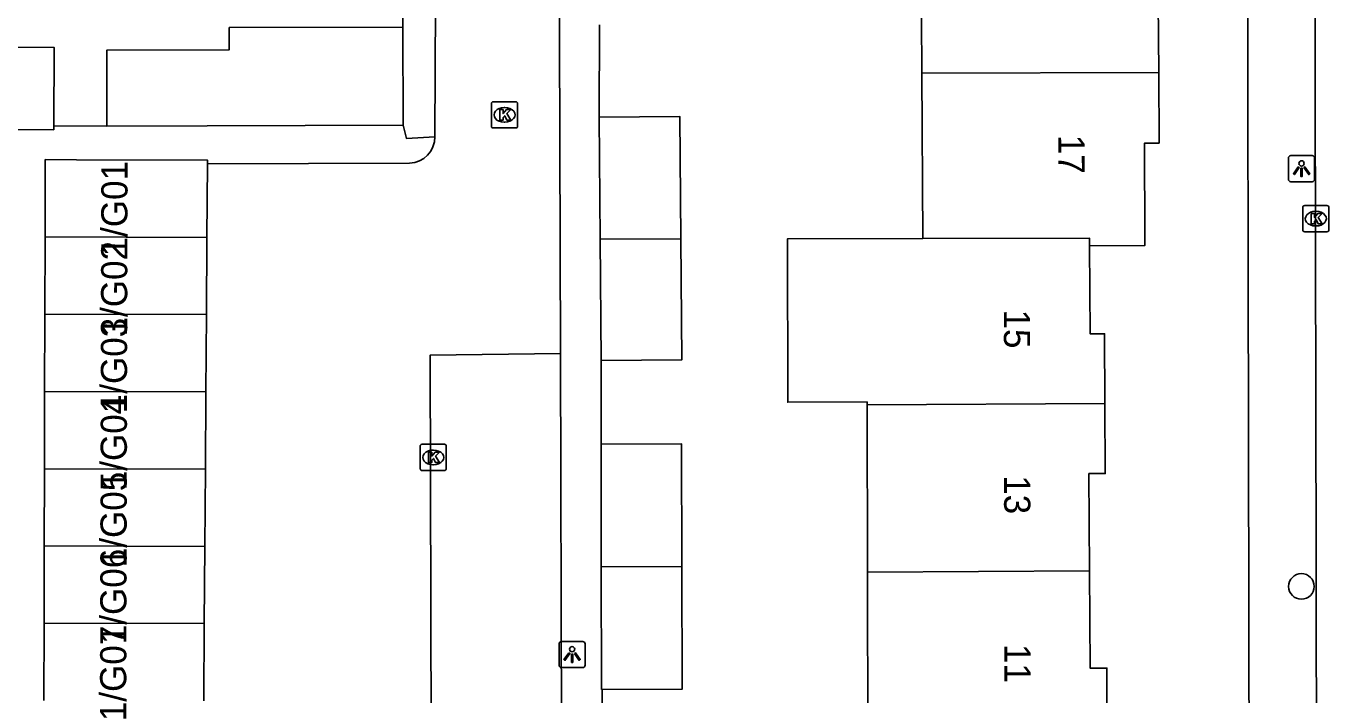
# Model space of a CAD drawing. Extents: x 160732 to 162105, y 387428 to 388479.
# Drawn here: x 161107.53 to 161157.26, y 387901.19 to 387926.72 of the extents above; entities that cross this region are included whole.
import ezdxf

# ---------------------------------------------------------------- set-up
doc = ezdxf.new("R2010")
doc.units = 0
for name, color, linetype in [('IMGEO_Boom', 7, 'Continuous'), ('IMGEO_Kolk', 7, 'Continuous'), ('IMGEO_Lichtpunt', 7, 'Continuous'), ('IMGEO_Muur', 7, 'Continuous'), ('IMGEO_Pand', 7, 'Continuous'), ('IMGEO_Pand_nummerreeks', 7, 'Continuous'), ('IMGEO_Rijbaan_lokaal_open', 7, 'Continuous'), ('IMGEO_Voetpad_open', 7, 'Continuous')]:
    doc.layers.add(name, color=color, linetype=linetype)

msp = doc.modelspace()

# ---------------------------------------------------------------- linework, layer by layer
at = {"layer": 'IMGEO_Boom'}
msp.add_circle((161156.212, 387905.33), 0.489, dxfattribs=at)
at = {"layer": 'IMGEO_Kolk'}
for p, q in [((161125.292, 387922.907), (161125.292, 387923.759)), ((161125.367, 387923.833), (161126.219, 387923.833)), ((161125.78, 387923.613), (161125.805, 387923.613)), ((161126.293, 387923.759), (161126.293, 387922.907)), ((161125.803, 387923.053), (161125.778, 387923.053)), ((161126.219, 387922.833), (161125.367, 387922.833)), ((161156.262, 387918.946), (161156.262, 387919.798)), ((161156.337, 387919.872), (161157.189, 387919.872)), ((161156.75, 387919.652), (161156.775, 387919.652)), ((161157.263, 387919.798), (161157.263, 387918.946)), ((161156.773, 387919.092), (161156.748, 387919.092)), ((161157.189, 387918.872), (161156.337, 387918.872)), ((161122.57, 387909.83), (161122.57, 387910.682)), ((161122.645, 387910.756), (161123.497, 387910.756)), ((161123.058, 387910.536), (161123.083, 387910.536)), ((161123.571, 387910.682), (161123.571, 387909.83)), ((161123.081, 387909.976), (161123.056, 387909.976)), ((161123.497, 387909.756), (161122.645, 387909.756))]:
    msp.add_line(p, q, dxfattribs=at)
for points in [[(161125.292, 387922.907), (161125.292, 387923.759)], [(161125.367, 387923.833), (161126.219, 387923.833)], [(161125.613, 387923.533), (161125.736, 387923.533), (161125.736, 387923.382), (161125.866, 387923.533), (161126.03, 387923.533), (161125.884, 387923.382), (161126.037, 387923.133), (161125.885, 387923.133), (161125.8, 387923.297), (161125.736, 387923.23), (161125.736, 387923.133), (161125.613, 387923.133), (161125.613, 387923.533)], [(161126.293, 387923.759), (161126.293, 387922.907)], [(161126.219, 387922.833), (161125.367, 387922.833)], [(161156.262, 387918.946), (161156.262, 387919.798)], [(161156.337, 387919.872), (161157.189, 387919.872)], [(161156.583, 387919.572), (161156.706, 387919.572), (161156.706, 387919.421), (161156.836, 387919.572), (161157, 387919.572), (161156.854, 387919.421), (161157.007, 387919.172), (161156.855, 387919.172), (161156.77, 387919.336), (161156.706, 387919.269), (161156.706, 387919.172), (161156.583, 387919.172), (161156.583, 387919.572)], [(161157.263, 387919.798), (161157.263, 387918.946)], [(161157.189, 387918.872), (161156.337, 387918.872)], [(161122.57, 387909.83), (161122.57, 387910.682)], [(161122.645, 387910.756), (161123.497, 387910.756)], [(161122.891, 387910.456), (161123.014, 387910.456), (161123.014, 387910.305), (161123.144, 387910.456), (161123.308, 387910.456), (161123.162, 387910.305), (161123.315, 387910.056), (161123.163, 387910.056), (161123.078, 387910.22), (161123.014, 387910.153), (161123.014, 387910.056), (161122.891, 387910.056), (161122.891, 387910.456)], [(161123.571, 387910.682), (161123.571, 387909.83)], [(161123.497, 387909.756), (161122.645, 387909.756)]]:
    msp.add_lwpolyline(points, dxfattribs=at)
for centre, start, end in [((161125.369, 387923.757), 91.552, 178.448), ((161125.369, 387923.757), 91.552, 178.448), ((161126.217, 387923.757), 1.552, 88.448), ((161126.217, 387923.757), 1.552, 88.448), ((161125.369, 387922.909), 181.552, 268.448), ((161125.369, 387922.909), 181.552, 268.448), ((161126.217, 387922.909), 271.552, 358.448), ((161126.217, 387922.909), 271.552, 358.448), ((161156.339, 387919.796), 91.552, 178.448), ((161156.339, 387919.796), 91.552, 178.448), ((161157.187, 387919.796), 1.552, 88.448), ((161157.187, 387919.796), 1.552, 88.448), ((161156.339, 387918.948), 181.552, 268.448), ((161156.339, 387918.948), 181.552, 268.448), ((161157.187, 387918.948), 271.552, 358.448), ((161157.187, 387918.948), 271.552, 358.448), ((161122.647, 387910.68), 91.552, 178.448), ((161122.647, 387910.68), 91.552, 178.448), ((161123.495, 387910.68), 1.552, 88.448), ((161123.495, 387910.68), 1.552, 88.448), ((161122.647, 387909.832), 181.552, 268.448), ((161122.647, 387909.832), 181.552, 268.448), ((161123.495, 387909.832), 271.552, 358.448), ((161123.495, 387909.832), 271.552, 358.448)]:
    msp.add_arc(centre, 0.0765, start, end, dxfattribs=at)
for centre, major_axis, ratio, start_param, end_param in [((161125.779, 387923.333), (-0.387, 0.002), 0.722429, 4.712389, 7.853982), ((161125.804, 387923.333), (-0.39, 0.002), 0.717154, 1.570796, 4.712389), ((161156.749, 387919.372), (-0.387, 0.002), 0.722429, 4.712389, 7.853982), ((161156.774, 387919.372), (-0.39, 0.002), 0.717154, 1.570796, 4.712389), ((161123.057, 387910.256), (-0.387, 0.002), 0.722429, 4.712389, 7.853982), ((161123.082, 387910.256), (-0.39, 0.002), 0.717154, 1.570796, 4.712389)]:
    msp.add_ellipse(centre, major_axis=major_axis, ratio=ratio, start_param=start_param, end_param=end_param, dxfattribs=at)
at = {"layer": 'IMGEO_Lichtpunt'}
for p, q in [((161155.718, 387921.683), (161155.718, 387920.876)), ((161155.718, 387921.683), (161155.718, 387920.876)), ((161156.62, 387921.778), (161155.812, 387921.778)), ((161156.62, 387921.778), (161155.812, 387921.778)), ((161156.714, 387920.876), (161156.714, 387921.683)), ((161156.714, 387920.876), (161156.714, 387921.683)), ((161155.812, 387920.782), (161156.62, 387920.782)), ((161155.812, 387920.782), (161156.62, 387920.782)), ((161127.875, 387903.134), (161127.875, 387902.327)), ((161127.875, 387903.134), (161127.875, 387902.327)), ((161128.777, 387903.229), (161127.969, 387903.229)), ((161128.777, 387903.229), (161127.969, 387903.229)), ((161128.871, 387902.327), (161128.871, 387903.134)), ((161128.871, 387902.327), (161128.871, 387903.134)), ((161127.969, 387902.233), (161128.777, 387902.233)), ((161127.969, 387902.233), (161128.777, 387902.233))]:
    msp.add_line(p, q, dxfattribs=at)
for points in [[(161156.092, 387921.347), (161156.131, 387921.319), (161155.943, 387921.057), (161155.905, 387921.084), (161156.092, 387921.347)], [(161156.194, 387921.299), (161156.241, 387921.299), (161156.241, 387920.977), (161156.194, 387920.977), (161156.194, 387921.299)], [(161156.304, 387921.319), (161156.342, 387921.346), (161156.529, 387921.084), (161156.49, 387921.056), (161156.304, 387921.319)], [(161128.249, 387902.798), (161128.288, 387902.77), (161128.1, 387902.508), (161128.062, 387902.535), (161128.249, 387902.798)], [(161128.351, 387902.75), (161128.398, 387902.75), (161128.398, 387902.428), (161128.351, 387902.428), (161128.351, 387902.75)], [(161128.461, 387902.77), (161128.499, 387902.797), (161128.686, 387902.535), (161128.647, 387902.507), (161128.461, 387902.77)]]:
    msp.add_lwpolyline(points, dxfattribs=at)
for centre in [(161156.217, 387921.481), (161128.374, 387902.932)]:
    msp.add_circle(centre, 0.0994, dxfattribs=at)
for centre, start, end in [((161155.812, 387921.683), 90, 180), ((161155.812, 387921.683), 90, 180), ((161156.62, 387921.683), 0, 90), ((161156.62, 387921.683), 0, 90), ((161155.812, 387920.876), 180, 270), ((161155.812, 387920.876), 180, 270), ((161156.62, 387920.876), 270, 0), ((161156.62, 387920.876), 270, 360), ((161127.969, 387903.134), 90, 180), ((161127.969, 387903.134), 90, 180), ((161128.777, 387903.134), 0, 90), ((161128.777, 387903.134), 0, 90), ((161127.969, 387902.327), 180, 270), ((161127.969, 387902.327), 180, 270), ((161128.777, 387902.327), 270, 0), ((161128.777, 387902.327), 270, 360)]:
    msp.add_arc(centre, 0.0946, start, end, dxfattribs=at)
at = {"layer": 'IMGEO_Muur'}
msp.add_lwpolyline([(161121.921, 387927.626), (161121.915, 387926.685)], dxfattribs=at)
at = {"layer": 'IMGEO_Pand'}
for points in [[(161141.685, 387931.353), (161141.721, 387924.932)], [(161150.765, 387924.948), (161150.75, 387927.642), (161150.13, 387927.638), (161150.109, 387931.368)], [(161110.618, 387922.905), (161110.608, 387925.803), (161115.287, 387925.818), (161115.285, 387926.663), (161121.915, 387926.685)], [(161121.928, 387922.943), (161121.915, 387926.685)], [(161108.586, 387922.912), (161108.596, 387925.912), (161102.178, 387925.935)], [(161150.765, 387924.948), (161141.721, 387924.932)], [(161141.721, 387924.932), (161141.757, 387918.614)], [(161148.128, 387918.338), (161150.24, 387918.35), (161150.238, 387918.629), (161150.218, 387922.251), (161150.781, 387922.254), (161150.765, 387924.948)], [(161108.586, 387922.912), (161108.585, 387922.765), (161102.19, 387922.788)], [(161121.928, 387922.943), (161114.448, 387922.918), (161110.618, 387922.905)], [(161129.402, 387923.242), (161132.486, 387923.268), (161132.524, 387918.598)], [(161129.441, 387918.592), (161129.402, 387923.242)], [(161114.453, 387921.466), (161114.454, 387921.609), (161109.455, 387921.622), (161108.261, 387921.624), (161108.253, 387918.674)], [(161114.434, 387918.658), (161114.453, 387921.466)], [(161108.253, 387918.674), (161108.246, 387915.724)], [(161108.253, 387918.674), (161114.434, 387918.658)], [(161114.413, 387915.708), (161114.434, 387918.658)], [(161129.441, 387918.592), (161132.524, 387918.598)], [(161129.479, 387913.961), (161129.441, 387918.592)], [(161132.524, 387918.598), (161132.562, 387913.986), (161129.479, 387913.961)], [(161141.757, 387918.614), (161136.601, 387918.605), (161136.605, 387912.363), (161139.633, 387912.373), (161139.633, 387912.259)], [(161141.757, 387918.614), (161148.126, 387918.625), (161148.128, 387918.338)], [(161148.712, 387912.31), (161148.697, 387914.979), (161148.147, 387914.976), (161148.128, 387918.338)], [(161108.246, 387915.724), (161108.238, 387912.775)], [(161114.413, 387915.708), (161108.246, 387915.724)], [(161114.393, 387912.759), (161114.413, 387915.708)], [(161108.238, 387912.775), (161108.23, 387909.825)], [(161114.393, 387912.759), (161108.238, 387912.775)], [(161114.373, 387909.809), (161114.393, 387912.759)], [(161148.712, 387912.31), (161139.633, 387912.259)], [(161139.633, 387912.259), (161139.648, 387905.871)], [(161148.122, 387905.922), (161148.101, 387909.637), (161148.726, 387909.641), (161148.712, 387912.31)], [(161129.479, 387910.767), (161132.553, 387910.772), (161132.562, 387906.088)], [(161129.488, 387906.082), (161129.479, 387910.767)], [(161108.23, 387909.825), (161108.223, 387906.875)], [(161108.23, 387909.825), (161114.373, 387909.809)], [(161114.353, 387906.859), (161114.373, 387909.809)], [(161108.223, 387906.875), (161108.215, 387903.925)], [(161114.353, 387906.859), (161108.223, 387906.875)], [(161114.332, 387903.909), (161114.353, 387906.859)], [(161129.488, 387906.082), (161132.562, 387906.088)], [(161129.516, 387901.399), (161129.497, 387901.399), (161129.488, 387906.082)], [(161132.562, 387906.088), (161132.57, 387901.405), (161129.516, 387901.399)], [(161139.648, 387905.871), (161148.122, 387905.922)], [(161139.648, 387905.871), (161139.662, 387899.466)], [(161148.799, 387899.508), (161148.787, 387902.215), (161148.143, 387902.212), (161148.122, 387905.922)], [(161108.208, 387900.976), (161108.215, 387903.925)], [(161108.215, 387903.925), (161114.332, 387903.909)], [(161114.332, 387903.909), (161114.312, 387900.96)]]:
    msp.add_lwpolyline(points, dxfattribs=at)
at = {"layer": 'IMGEO_Rijbaan_lokaal_open'}
for points in [[(161156.704, 387942.547), (161156.776, 387906.254), (161156.817, 387879.896)], [(161127.926, 387914.225), (161127.885, 387930.449)], [(161123.156, 387927.578), (161123.128, 387922.5)], [(161114.453, 387921.466), (161122.168, 387921.485)], [(161123.049, 387880.357), (161122.958, 387914.162), (161127.926, 387914.225)]]:
    msp.add_lwpolyline(points, dxfattribs=at)
msp.add_arc((161122.14, 387922.473), 0.989, 271.6458, 1.5446, dxfattribs=at)
at = {"layer": 'IMGEO_Voetpad_open'}
for points in [[(161154.127, 387944.025), (161154.217, 387897.663), (161154.171, 387880.36)], [(161121.915, 387926.685), (161121.921, 387927.626)], [(161129.42, 387926.772), (161129.402, 387923.242)], [(161110.618, 387922.905), (161108.586, 387922.912)], [(161123.128, 387922.5), (161122.048, 387922.435), (161121.928, 387922.943)], [(161127.926, 387914.225), (161127.963, 387899.767)], [(161129.479, 387913.961), (161129.479, 387910.767)], [(161129.516, 387901.399), (161129.514, 387899.541)]]:
    msp.add_lwpolyline(points, dxfattribs=at)

# ---------------------------------------------------------------- texts
at = {"layer": 'IMGEO_Pand_nummerreeks'}
for s, rotation, p in [('17', 270.3894, (161146.932, 387922.568)), ('1/G01', 89.8549, (161111.396, 387917.929)), ('1/G02', 89.8549, (161111.388, 387914.874)), ('1/G03', 89.8549, (161111.381, 387911.941)), ('15', 270.1029, (161144.853, 387915.903)), ('1/G04', 89.8549, (161111.373, 387909.002)), ('1/G05', 89.8549, (161111.366, 387906.063)), ('13', 270.1026, (161144.863, 387909.576)), ('1/G06', 89.8549, (161111.358, 387903.124)), ('1/G07', 89.8549, (161111.351, 387900.185)), ('11', 270.1026, (161144.874, 387903.135))]:
    msp.add_text(s, height=1, rotation=rotation, dxfattribs=at).set_placement(p)

doc.saveas('drawing.dxf')
